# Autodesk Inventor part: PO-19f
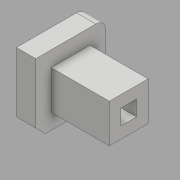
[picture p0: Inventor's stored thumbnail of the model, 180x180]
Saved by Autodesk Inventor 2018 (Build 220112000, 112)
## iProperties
Created: 2020-01
Part Number: PO-19f
Material: Générique
Document SubType Name: Modeling
Designer: TJ
Density: 1 g/cm^3
Appearance: Par défaut
Author: TJ
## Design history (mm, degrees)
sketch "Esquisse1"
  geometry: L1 (18, 18)-(-18, 18); L2 (-18, 18)-(-18, -18); L3 (-18, -18)-(18, -18); L4 (18, -18)-(18, 18); 1 further point
  constraints: 8 end point, 2 parallel, 1 horizontal, 1 perpendicular
  dimensions: "d0" = 36 distance of L3.end L1.start; "d1" = 36 distance of L1.start L1.end (= d0); "d2" = 18 distance from line of L4 point (0, 0) (= 0.5 x d0); "d3" = 18 distance from line of L1 point (0, 0) (= 0.5 x d0)
extrude "Extrusion1" new body sketch "Esquisse1" distance "d4" = 10; taper "d5" = 0 deg
sketch "Esquisse3"
  geometry: L1 (-10, 10)-(10, 10); L2 (10, 10)-(10, -10); L3 (10, -10)-(-10, -10); L4 (-10, -10)-(-10, 10); L5 (-10, 10)-(10, -10); L6 (10, 10)-(-10, -10); 1 further point
  constraints: 12 end point, 2 midpoint, 2 parallel, 1 horizontal, 1 perpendicular
  dimensions: "d10" = 20 distance of L1.start L1.end; "d11" = 20 distance of L3.end L1.start (= d10)
extrude "Extrusion3" join sketch "Esquisse3" distance "d12" = 30; taper "d13" = 0 deg
sketch "Esquisse5"
  geometry: L1 (-4, -4)-(4, -4); L2 (4, -4)-(4, 4); L3 (4, 4)-(-4, 4); L4 (-4, 4)-(-4, -4); L5 (-4, -4)-(4, 4); L6 (4, -4)-(-4, 4); 1 further point
  constraints: 12 end point, 2 midpoint, 2 parallel, 1 horizontal, 1 perpendicular
  dimensions: "d17" = 8 distance of L3.end L1.start; "d18" = 8 distance of L2.end L3.end
extrude "Extrusion5" cut sketch "Esquisse5" extent not by distance; stored distance "d19" = 10; taper "d20" = 0 deg
fillet "Congé2" dims "d21" = 5
chamfer "Chanfrein1" distance "d22" = 5; stored, may be unused: second distance "d23" = 2, angle "d24" = 45 deg
node "Solide1"
